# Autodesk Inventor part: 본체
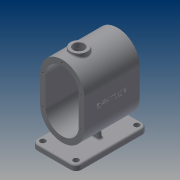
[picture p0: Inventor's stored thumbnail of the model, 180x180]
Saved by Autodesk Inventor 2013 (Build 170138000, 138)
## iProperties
Created: 2016-12
Part Number: 본체
Material: 알루미늄 6061
Document SubType Name: Modeling
Designer: mduedu
Density: 2.71 g/cm^3
Mass: 1146.21 g
Surface Area: 978.82 cm^2
Volume: 422.955 cm^3
Author: mduedu
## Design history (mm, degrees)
sketch "스케치1"
  geometry: L1 (40, -25)-(40, 25); L2 (-40, 25)-(-40, -25); L3 (-40, -25)-(40, 25); L4 (40, -25)-(-40, 25); L5 (0, 25)-(0, -25); A1 r 40 centre (0, 25) between (40, 25) and (-40, 25); A2 r 40 centre (0, -25) between (-40, -25) and (40, -25); 1 further point
  constraints: 10 end point, 4 point on circle, 3 tangent, 2 centre point, 2 midpoint, 2 parallel, 1 vertical
  dimensions: "d0" = 130 dimension on A2 A1; "d2" = 80 distance between parallel lines of L1 L2
extrude "돌출1" new body sketch "스케치1" stored distance "d3" = 100; taper "d4" = 0 deg
feature "쉘1" dims "d5" = 10
sketch "스케치2"
  geometry: L1 (-75, 65)-(-85, 65); L2 (-85, 65)-(-85, -65); L3 (-85, -65)-(-75, -65); L4 (-75, -65)-(-75, 65); 2 further points
  constraints: 8 end point, 2 parallel, 1 horizontal, 1 horizontal alignment, 1 midpoint, 1 perpendicular
  dimensions: "d6" = 85 distance from line of L2 point (0, 0); "d7" = 130 distance of L1.end L2.end; "d8" = 10 distance of L2.end L3.end
extrude "돌출2" join sketch "스케치2" stored distance "d9" = 80; taper "d10" = 0 deg
fillet "모깎기1" dims "d11" = 10
sketch "스케치3"
  geometry: L1 (-10, 10)-(-10, 120) reference; L2 (60, 0)-(0, 0) reference; L3 (70, 120)-(70, 10) reference; L4 (0, 130)-(60, 130) reference; A1 r 10 centre (0, 120) between (0, 130) and (-10, 120) reference; A2 r 10 centre (0, 10) between (-10, 10) and (0, 0) reference; A3 r 10 centre (60, 10) between (60, 0) and (70, 10) reference; A4 r 10 centre (60, 120) between (70, 120) and (60, 130) reference; 5 further points
  constraints: 4 coincident
hole "구멍1" sketch "스케치3" at (60, 120), (60, 10), (0, 10), (0, 120) diameter "d12" = 10; stored, may be unused: countersink angle "d16" = 90 deg, drill point angle "d18" = 118 deg; dims "d13" = 6, "d14" = 4, "d15" = 2, "d17" = 8
sketch "스케치5"
  geometry: L1 (34, 35)-(26, 35); L2 (26, 35)-(26, 95); L3 (26, 95)-(34, 95); L4 (34, 95)-(34, 35); L5 (34, 35)-(26, 95); L6 (26, 35)-(34, 95); 1 further point
  constraints: 12 end point, 2 midpoint, 2 parallel, 1 horizontal, 1 perpendicular
  dimensions: "d22" = 8 distance of L2.end L3.end; "d24" = 60 distance of L1.end L2.end
extrude "돌출3" join sketch "스케치5" stored distance "d25" = 80; taper "d26" = 0 deg
feature "면 기울기1" dims angle "d27" = 5 deg
sketch "스케치6"
  geometry: L1 (-30, -75)-(30, -75) reference; L2 (-17.524, -60.957)-(-20, -75); A1 r 40 centre (0, -25) between (-40, -25) and (40, -25) reference; 1 further point
  constraints: 2 end point, 1 point on circle, 1 point on line
  dimensions: "d28" = 20 horizontal distance of A1.centre L2.end; "d29" = 80 deg angle of L2 L1
feature "리브1" sketch "스케치6" dims "d30" = 1, "d31" = 8, "d32" = 0, "d33" = 0, "d34" = 1, "d35" = 1
fillet "모깎기2" dims "d36" = 3
fillet "모깎기3" dims "d37" = 3, "d38" = 3
node "작업 평면1"
sketch "스케치9"
  geometry: 1 further point
sketch "스케치7"
  geometry: L1 (40, 50)-(-40, 50) reference; C1 r 15 at (0, 20); 1 further point
  constraints: 1 centre point, 1 vertical alignment
  dimensions: "d40" = 30 diameter of C1; "d41" = 30 distance from line of C1.centre L1
extrude "돌출4" join sketch "스케치7" stored distance "d42" = 80; taper "d43" = 0 deg
hole "구멍2" diameter "d46" = 20; stored, may be unused: countersink angle "d50" = 90 deg, drill point angle "d52" = 118 deg; dims "d44" = 10, "d45" = 10, "d47" = 6, "d48" = 4, "d49" = 2, "d51" = 8
fillet "모깎기4" dims "d53" = 3
node "작업 평면2"
sketch "스케치8"
  geometry: C1 r 15 at (0, 0) reference; C2 r 15 at (0, 0); 1 further point
  constraints: 1 centre point, 1 coincident
  dimensions: "d55" = 30 diameter of C2
extrude "돌출5" cut sketch "스케치8" stored distance "d56" = 80; taper "d57" = 0 deg
chamfer "모따기1" distance "d58" = 1; stored, may be unused: second distance "d59" = 2, angle "d60" = 45 deg
sketch "스케치10"
  geometry: 2 further points
  constraints: 1 coincident, 1 other
feature "엠보싱1" sketch "스케치10" dims "d0" = 130, "d2" = 80, "d61" = 0.5, "d62" = 0
sketch "스케치11"
  geometry: 1 further point
hole "구멍3" sketch "스케치11" at (0, 60) diameter "d63" = 3.242; stored, may be unused: countersink angle "d67" = 90 deg, drill point angle "d69" = 120 deg; dims "d64" = 8.6, "d65" = 4, "d66" = 2, "d68" = 10.6
sketch "스케치12"
  geometry: 1 further point
hole "구멍5" sketch "스케치12" at (0, 60) diameter "d70" = 3.242; stored, may be unused: countersink angle "d74" = 90 deg, drill point angle "d76" = 120 deg; dims "d71" = 8.6, "d72" = 4, "d73" = 2, "d75" = 10.6
node "솔리드1"
mirror "대칭1"
pattern_linear "직사각형 패턴1"
pattern_linear "직사각형 패턴2"
node "투영된 루프1"
sketch "스케치13"
  geometry: L1 (-40, 25)-(-40, -25) reference; L2 (40, -25)-(40, 25) reference; L3 (35, 25)-(35, -25); L4 (-35, -25)-(-35, 25); A1 r 40 centre (0, 25) between (40, 25) and (-40, 25) reference; A2 r 40 centre (0, -25) between (-40, -25) and (40, -25) reference; A3 r 35 centre (0, 25) between (35, 25) and (-35, 25); A4 r 35 centre (0, -25) between (-35, -25) and (35, -25); 2 further points
  constraints: 5 point on circle, 4 end point, 2 centre point, 3 other
  dimensions: "d77" = 5 distance between parallel lines of L3 L2
sketch "스케치14"
  geometry: L1 (-40, 25)-(-40, -25) reference; L2 (40, -25)-(40, 25) reference; L3 (35, 25)-(35, -25); L4 (-35, -25)-(-35, 25); A1 r 40 centre (0, 25) between (40, 25) and (-40, 25) reference; A2 r 40 centre (0, -25) between (-40, -25) and (40, -25) reference; A3 r 35 centre (0, 25) between (35, 25) and (-35, 25); A4 r 35 centre (0, -25) between (-35, -25) and (35, -25); 2 further points
  constraints: 5 point on circle, 4 end point, 2 centre point, 3 other
  dimensions: "d80" = 5 distance between parallel lines of L2 L3
